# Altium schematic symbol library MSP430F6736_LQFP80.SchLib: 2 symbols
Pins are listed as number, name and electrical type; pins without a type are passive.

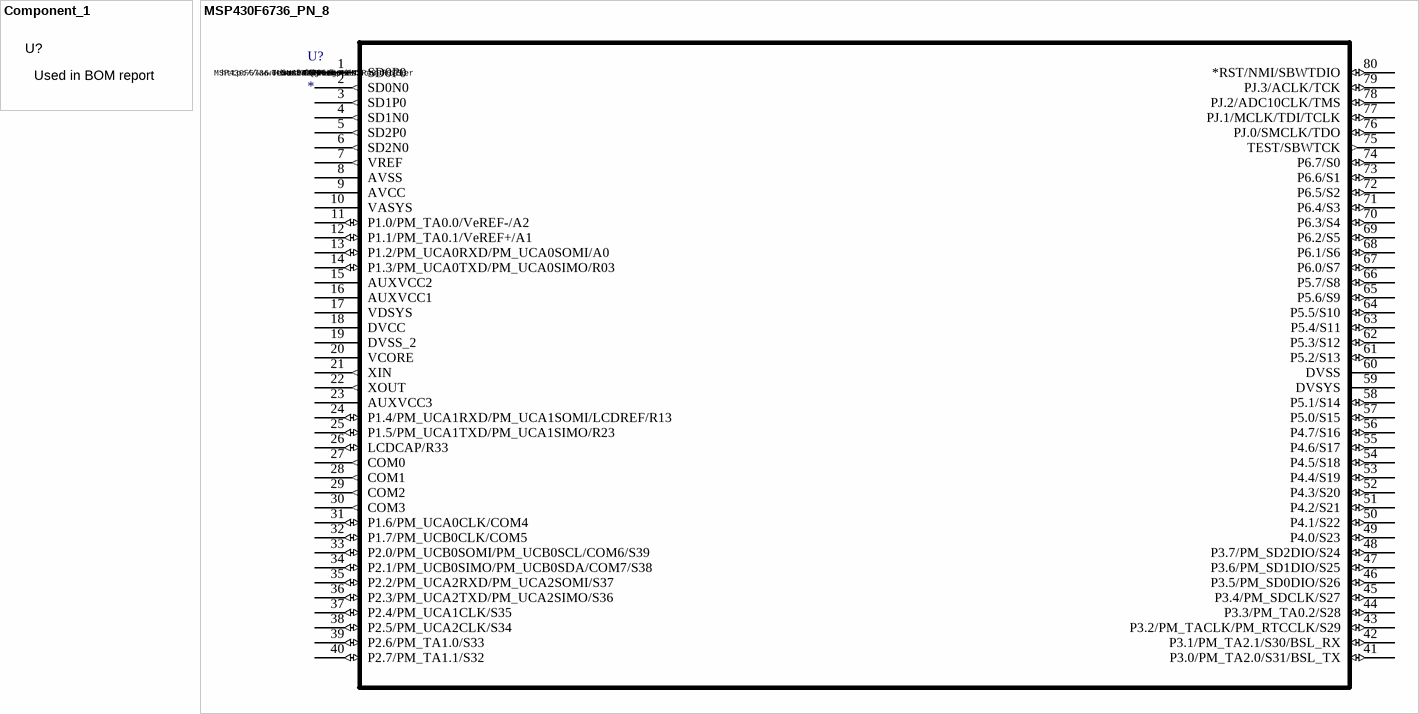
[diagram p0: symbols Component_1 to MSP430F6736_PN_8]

## Component_1
designator U?, comment Used in BOM report
SymbolVersion: use current date i.e. 2008-05-20; SymbolCreator: Use a-id; CompType: Used in some BOM reports.  Useful for finding later.; U/M: EA, IN, or GM

## MSP430F6736_PN_8
designator U?  VENDOR: Texas Instruments  MANUFACTURER_PART_NUMBER: msp430f6736_pn_80  GENERIC_PART_NUMBER: MSP430F6736  DESCRIPTION: MSP430F6736 Mixed Signal Microcontroller  PACKAGE_DESIGNATOR: PN  PIN_COUNT: 80  FAMILY_NAME: 6 Series with LCD  INDUSTRY_STD_PKG_TYPE: LQFP
Imported
footprint PN80
pins: 1 SD0P0 (out), 2 SD0N0 (out), 3 SD1P0 (out), 4 SD1N0 (out), 5 SD2P0 (out), 6 SD2N0 (out), 7 VREF (out), 8 AVSS (power), 9 AVCC (power), 10 VASYS (power), 11 P1.0/PM_TA0.0/VeREF-/A2 (io), 12 P1.1/PM_TA0.1/VeREF+/A1 (io), 13 P1.2/PM_UCA0RXD/PM_UCA0SOMI/A0 (io), 14 P1.3/PM_UCA0TXD/PM_UCA0SIMO/R03 (io), 15 AUXVCC2 (power), 16 AUXVCC1 (power), 17 VDSYS (power), 18 DVCC (power), 19 DVSS_2 (power), 20 VCORE (power), 21 XIN (out), 22 XOUT (out), 23 AUXVCC3 (power), 24 P1.4/PM_UCA1RXD/PM_UCA1SOMI/LCDREF/R13 (io), 25 P1.5/PM_UCA1TXD/PM_UCA1SIMO/R23 (io), 26 LCDCAP/R33 (io), 27 COM0 (out), 28 COM1 (out), 29 COM2 (out), 30 COM3 (out), 31 P1.6/PM_UCA0CLK/COM4 (io), 32 P1.7/PM_UCB0CLK/COM5 (io), 33 P2.0/PM_UCB0SOMI/PM_UCB0SCL/COM6/S39 (io), 34 P2.1/PM_UCB0SIMO/PM_UCB0SDA/COM7/S38 (io), 35 P2.2/PM_UCA2RXD/PM_UCA2SOMI/S37 (io), 36 P2.3/PM_UCA2TXD/PM_UCA2SIMO/S36 (io), 37 P2.4/PM_UCA1CLK/S35 (io), 38 P2.5/PM_UCA2CLK/S34 (io), 39 P2.6/PM_TA1.0/S33 (io), 40 P2.7/PM_TA1.1/S32 (io), 41 P3.0/PM_TA2.0/S31/BSL_TX (io), 42 P3.1/PM_TA2.1/S30/BSL_RX (io), 43 P3.2/PM_TACLK/PM_RTCCLK/S29 (io), 44 P3.3/PM_TA0.2/S28 (io), 45 P3.4/PM_SDCLK/S27 (io), 46 P3.5/PM_SD0DIO/S26 (io), 47 P3.6/PM_SD1DIO/S25 (io), 48 P3.7/PM_SD2DIO/S24 (io), 49 P4.0/S23 (io), 50 P4.1/S22 (io), 51 P4.2/S21 (io), 52 P4.3/S20 (io), 53 P4.4/S19 (io), 54 P4.5/S18 (io), 55 P4.6/S17 (io), 56 P4.7/S16 (io), 57 P5.0/S15 (io), 58 P5.1/S14 (io), 59 DVSYS (power), 60 DVSS (power), 61 P5.2/S13 (io), 62 P5.3/S12 (io), 63 P5.4/S11 (io), 64 P5.5/S10 (io), 65 P5.6/S9 (io), 66 P5.7/S8 (io), 67 P6.0/S7 (io), 68 P6.1/S6 (io), 69 P6.2/S5 (io), 70 P6.3/S4 (io), 71 P6.4/S3 (io), 72 P6.5/S2 (io), 73 P6.6/S1 (io), 74 P6.7/S0 (io), 75 TEST/SBWTCK (out), 76 PJ.0/SMCLK/TDO (io), 77 PJ.1/MCLK/TDI/TCLK (io), 78 PJ.2/ADC10CLK/TMS (io), 79 PJ.3/ACLK/TCK (io), 80 *RST/NMI/SBWTDIO (io)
